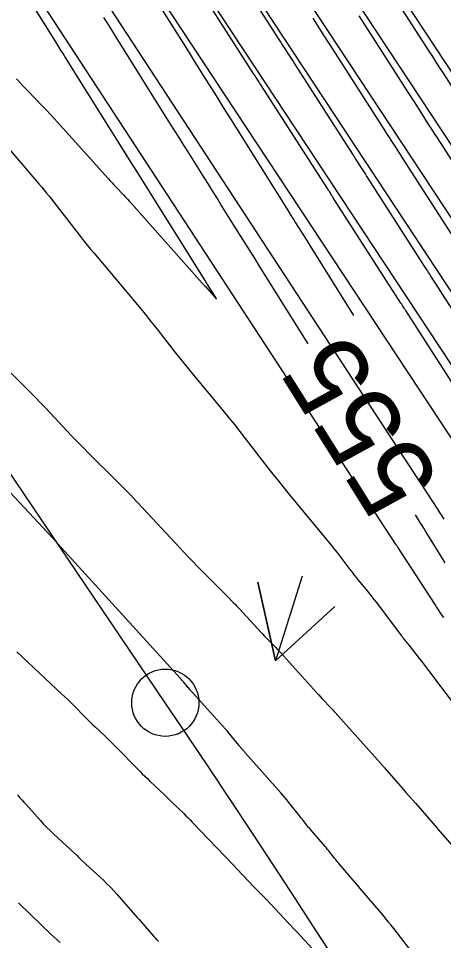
# Model space of a CAD drawing. Extents: x 954385 to 988206, y 1868364 to 1924553.
# Drawn here: x 957686 to 957717.7, y 1920041.8 to 1920110.4 of the extents above; entities that cross this region are included whole.
import ezdxf

# ---------------------------------------------------------------- set-up
doc = ezdxf.new("R2010")
doc.units = 0
for name, color, linetype in [('1', 7, 'Continuous'), ('Default', 7, 'Continuous'), ('Ex_Contour Labels', 7, 'Continuous'), ('Ex_Major Contours', 7, 'Continuous'), ('Ex_Minor Contours', 7, 'Continuous'), ('Prop_Horiz Alignment', 7, 'Continuous'), ('Slopes', 7, 'Continuous')]:
    doc.layers.add(name, color=color, linetype=linetype)

msp = doc.modelspace()

# ---------------------------------------------------------------- linework, layer by layer
at = {"layer": '1'}
for points in [[(957698.283, 1920136.745), (957732.756, 1920084.44)], [(957730.333, 1920082.664), (957695.897, 1920134.914)], [(957693.262, 1920133.461), (957727.911, 1920080.887)], [(957725.489, 1920079.111), (957690.628, 1920132.007)], [(957723.067, 1920077.335), (957687.993, 1920130.554)], [(957720.645, 1920075.559), (957685.358, 1920129.1)], [(957682.718, 1920126.67), (957717.191, 1920073.906), (957717.352, 1920073.659), (957717.513, 1920073.412), (957717.674, 1920073.166)], [(957717.675, 1920065.82), (957717.638, 1920065.877), (957717.411, 1920066.229), (957717.381, 1920066.275), (957717.132, 1920066.659), (957717.022, 1920066.828), (957714.26, 1920071.08), (957714.23, 1920071.126), (957714.2, 1920071.171), (957714.17, 1920071.217), (957714.14, 1920071.263), (957679.353, 1920124.508)], [(957677.043, 1920110.41), (957687.555, 1920098.121), (957687.748, 1920097.893), (957687.939, 1920097.662), (957688.127, 1920097.43), (957688.313, 1920097.195), (957690.738, 1920094.097), (957690.959, 1920093.817), (957691.182, 1920093.539), (957691.408, 1920093.263), (957691.635, 1920092.989), (957695.137, 1920088.81), (957695.465, 1920088.414), (957695.79, 1920088.015), (957696.112, 1920087.614), (957696.429, 1920087.209), (957697.692, 1920085.585), (957698.01, 1920085.18), (957698.33, 1920084.778), (957698.654, 1920084.379), (957698.981, 1920083.981), (957701.267, 1920081.228), (957701.685, 1920080.72), (957702.098, 1920080.209), (957702.507, 1920079.694), (957702.911, 1920079.176), (957704.593, 1920077), (957704.96, 1920076.529), (957705.33, 1920076.062), (957705.704, 1920075.597), (957706.082, 1920075.135), (957709.172, 1920071.381), (957709.308, 1920071.215), (957709.441, 1920071.048), (957709.574, 1920070.88), (957709.705, 1920070.711), (957710.692, 1920069.424), (957710.851, 1920069.219), (957711.011, 1920069.015), (957711.172, 1920068.812), (957711.335, 1920068.61), (957711.99, 1920067.805), (957712.153, 1920067.604), (957712.314, 1920067.4), (957712.474, 1920067.196), (957712.631, 1920066.99), (957714.536, 1920064.478), (957714.567, 1920064.438), (957714.597, 1920064.398), (957714.627, 1920064.358), (957714.657, 1920064.318), (957714.81, 1920064.117), (957714.824, 1920064.097), (957714.839, 1920064.078), (957714.854, 1920064.059), (957714.869, 1920064.04), (957714.93, 1920063.965), (957714.96, 1920063.927), (957714.99, 1920063.889), (957715.869, 1920062.789), (957716.02, 1920062.599), (957716.169, 1920062.408), (957716.317, 1920062.215), (957716.463, 1920062.021), (957718.51, 1920059.276)], [(957715.109, 1920041.194), (957713.947, 1920042.705), (957713.747, 1920042.963), (957713.543, 1920043.218), (957713.337, 1920043.47), (957713.128, 1920043.72), (957711.45, 1920045.696), (957711.277, 1920045.9), (957711.105, 1920046.103), (957710.931, 1920046.305), (957710.758, 1920046.508), (957709.899, 1920047.511), (957709.808, 1920047.618), (957709.719, 1920047.725), (957709.632, 1920047.834), (957709.545, 1920047.943), (957709.201, 1920048.384), (957709.114, 1920048.493), (957709.026, 1920048.602), (957708.937, 1920048.709), (957708.846, 1920048.815), (957707.777, 1920050.051), (957707.698, 1920050.144), (957707.62, 1920050.237), (957707.542, 1920050.332), (957707.466, 1920050.428), (957707.163, 1920050.812), (957707.088, 1920050.908), (957707.012, 1920051.004), (957706.936, 1920051.099), (957706.86, 1920051.195), (957706.143, 1920052.096), (957705.997, 1920052.277), (957705.849, 1920052.456), (957705.698, 1920052.634), (957705.545, 1920052.809), (957702.934, 1920055.769), (957702.897, 1920055.811), (957702.859, 1920055.853), (957702.822, 1920055.896), (957702.784, 1920055.938), (957702.582, 1920056.165), (957702.571, 1920056.178), (957702.56, 1920056.191), (957702.549, 1920056.205), (957702.538, 1920056.218), (957702.484, 1920056.285), (957702.451, 1920056.326), (957701.861, 1920057.054), (957701.758, 1920057.179), (957701.654, 1920057.303), (957701.548, 1920057.425), (957701.44, 1920057.546), (957698.763, 1920060.519), (957698.704, 1920060.585), (957698.647, 1920060.651), (957698.59, 1920060.718), (957698.533, 1920060.786), (957698.31, 1920061.058), (957698.254, 1920061.125), (957698.197, 1920061.192), (957698.139, 1920061.258), (957698.08, 1920061.324), (957688.977, 1920071.325), (957688.97, 1920071.332), (957688.939, 1920071.367), (957688.931, 1920071.375), (957682.191, 1920078.59)], [(957685.956, 1920052.648), (957686.119, 1920052.468), (957686.282, 1920052.287), (957686.445, 1920052.107), (957686.608, 1920051.926), (957687.674, 1920050.742), (957687.909, 1920050.487), (957688.15, 1920050.238), (957688.397, 1920049.995), (957688.649, 1920049.758), (957690.293, 1920048.25), (957690.32, 1920048.224), (957690.347, 1920048.198), (957690.373, 1920048.171), (957690.398, 1920048.143), (957690.5, 1920048.028), (957690.525, 1920048.001), (957690.549, 1920047.976), (957690.575, 1920047.95), (957690.601, 1920047.926), (957690.706, 1920047.828), (957690.732, 1920047.804), (957690.759, 1920047.78), (957690.785, 1920047.755), (957690.811, 1920047.731), (957692.355, 1920046.296), (957692.617, 1920046.045), (957692.873, 1920045.788), (957693.123, 1920045.525), (957693.365, 1920045.255), (957694.867, 1920043.54), (957695.014, 1920043.372), (957695.161, 1920043.204), (957695.307, 1920043.036), (957695.454, 1920042.868), (957696.113, 1920042.109), (957696.223, 1920041.984), (957696.337, 1920041.862), (957696.453, 1920041.743)]]:
    msp.add_lwpolyline(points, dxfattribs=at)
at = {"layer": 'Default'}
msp.add_line((957696.959, 1920059.51), (957504.115, 1920344.606), dxfattribs=at)
msp.add_arc((956871.597, 1919501.221), 996.448, 12.648055, 34.075074, dxfattribs=at)
at = {"layer": 'Ex_Major Contours'}
for points in [[(957707.595, 1920086.214), (957703.976, 1920091.998), (957703.634, 1920092.544), (957703.292, 1920093.091), (957702.949, 1920093.637), (957702.607, 1920094.183), (957701.095, 1920096.598), (957700.784, 1920097.095), (957700.473, 1920097.592), (957700.161, 1920098.09), (957699.85, 1920098.587), (957698.604, 1920100.576), (957698.292, 1920101.074), (957697.981, 1920101.571), (957697.67, 1920102.068), (957697.358, 1920102.566), (957693.234, 1920109.157), (957692.953, 1920109.605), (957692.673, 1920110.053), (957692.392, 1920110.501)], [(957711.355, 1920110.617), (957711.571, 1920110.279), (957711.788, 1920109.941), (957714.673, 1920105.447), (957714.881, 1920105.123), (957715.09, 1920104.798), (957715.298, 1920104.473), (957715.506, 1920104.147), (957716.337, 1920102.847), (957716.545, 1920102.521), (957716.753, 1920102.196), (957716.961, 1920101.871), (957717.17, 1920101.546), (957720.151, 1920096.897)], [(957682.47, 1920086.987), (957686.457, 1920083.067), (957686.866, 1920082.661), (957687.271, 1920082.251), (957687.671, 1920081.837), (957688.068, 1920081.419), (957689.646, 1920079.74), (957690.043, 1920079.322), (957690.443, 1920078.907), (957690.846, 1920078.496), (957691.252, 1920078.087), (957693.386, 1920075.962), (957693.876, 1920075.47), (957694.36, 1920074.973), (957694.839, 1920074.472), (957695.314, 1920073.965), (957698.013, 1920071.056), (957698.34, 1920070.706), (957698.669, 1920070.36), (957699.002, 1920070.016), (957699.338, 1920069.676), (957701.135, 1920067.868), (957701.248, 1920067.754), (957701.362, 1920067.64), (957701.475, 1920067.525), (957701.588, 1920067.411), (957702.042, 1920066.953), (957702.154, 1920066.838), (957702.266, 1920066.722), (957702.377, 1920066.605), (957702.486, 1920066.487), (957704.087, 1920064.745), (957704.205, 1920064.618), (957704.324, 1920064.492), (957704.444, 1920064.367), (957704.565, 1920064.243), (957705.051, 1920063.748), (957705.172, 1920063.623), (957705.291, 1920063.498), (957705.41, 1920063.371), (957705.527, 1920063.243), (957708.206, 1920060.274), (957708.247, 1920060.229), (957708.287, 1920060.183), (957708.328, 1920060.138), (957708.369, 1920060.092), (957708.594, 1920059.838), (957708.603, 1920059.828), (957708.612, 1920059.818), (957708.621, 1920059.808), (957708.63, 1920059.799), (957708.677, 1920059.751), (957708.705, 1920059.722), (957709.228, 1920059.179), (957709.318, 1920059.084), (957709.407, 1920058.989), (957709.495, 1920058.893), (957709.582, 1920058.796), (957712.952, 1920055.002), (957712.977, 1920054.974), (957713.002, 1920054.946), (957713.027, 1920054.919), (957713.053, 1920054.892), (957713.155, 1920054.783), (957713.18, 1920054.756), (957713.205, 1920054.728), (957713.23, 1920054.701), (957713.255, 1920054.673), (957714.623, 1920053.109), (957714.859, 1920052.839), (957715.094, 1920052.569), (957715.33, 1920052.299), (957715.565, 1920052.028), (957717.18, 1920050.167), (957717.193, 1920050.151), (957717.207, 1920050.136), (957717.235, 1920050.106), (957717.242, 1920050.099), (957717.249, 1920050.091), (957717.256, 1920050.083), (957717.263, 1920050.076), (957718.271, 1920048.905)], [(957717.781, 1920069.93), (957716.406, 1920072.138), (957716.291, 1920072.323), (957716.176, 1920072.508), (957716.06, 1920072.692), (957715.945, 1920072.877), (957715.555, 1920073.5)]]:
    msp.add_lwpolyline(points, dxfattribs=at)
at = {"layer": 'Ex_Minor Contours'}
for points in [[(957685.882, 1920105.944), (957686.157, 1920105.648), (957686.435, 1920105.353), (957686.714, 1920105.06), (957687.836, 1920103.894), (957688.115, 1920103.601), (957688.392, 1920103.306), (957688.666, 1920103.009), (957688.938, 1920102.709), (957692.714, 1920098.512), (957692.855, 1920098.356), (957692.998, 1920098.201), (957693.141, 1920098.047), (957693.286, 1920097.894), (957693.866, 1920097.284), (957694.01, 1920097.13), (957694.153, 1920096.976), (957694.295, 1920096.82), (957694.436, 1920096.664), (957699.703, 1920090.734), (957699.722, 1920090.712), (957699.742, 1920090.69), (957699.763, 1920090.668), (957699.783, 1920090.646), (957699.864, 1920090.56), (957699.885, 1920090.538), (957699.905, 1920090.516), (957699.925, 1920090.494), (957699.944, 1920090.472), (957700.631, 1920089.694), (957700.725, 1920089.594), (957700.764, 1920089.566), (957700.749, 1920089.611), (957700.679, 1920089.73), (957699.984, 1920090.841), (957699.927, 1920090.933), (957694.739, 1920099.216), (957694.667, 1920099.33), (957694.596, 1920099.444), (957689.492, 1920107.599), (957689.426, 1920107.706), (957689.359, 1920107.812), (957689.293, 1920107.919), (957689.226, 1920108.025), (957688.892, 1920108.557), (957688.693, 1920108.877), (957684.243, 1920115.982)], [(957721.842, 1920083.274), (957717.409, 1920090.18), (957717.322, 1920090.315), (957717.235, 1920090.45), (957717.149, 1920090.585), (957717.062, 1920090.72), (957716.717, 1920091.26), (957716.63, 1920091.395), (957716.544, 1920091.53), (957716.457, 1920091.665), (957716.371, 1920091.8), (957712.024, 1920098.578), (957711.93, 1920098.724), (957711.837, 1920098.871), (957711.743, 1920099.017), (957711.65, 1920099.163), (957711.276, 1920099.747), (957711.182, 1920099.894), (957711.089, 1920100.04), (957710.995, 1920100.186), (957710.901, 1920100.332), (957706.637, 1920106.975), (957706.536, 1920107.132), (957706.435, 1920107.29), (957706.335, 1920107.447), (957706.234, 1920107.604), (957705.831, 1920108.234), (957705.731, 1920108.391), (957705.63, 1920108.549), (957705.529, 1920108.706), (957705.428, 1920108.863), (957701.251, 1920115.372)], [(957719.947, 1920080.734), (957714.837, 1920088.694), (957714.808, 1920088.741), (957714.778, 1920088.787), (957714.748, 1920088.834), (957714.718, 1920088.88), (957714.599, 1920089.066), (957714.54, 1920089.159), (957714.48, 1920089.251), (957709.451, 1920097.094), (957709.414, 1920097.151), (957709.378, 1920097.208), (957709.342, 1920097.264), (957709.306, 1920097.321), (957709.161, 1920097.548), (957709.125, 1920097.604), (957709.088, 1920097.661), (957709.052, 1920097.717), (957709.016, 1920097.774), (957704.061, 1920105.492), (957704.019, 1920105.559), (957703.976, 1920105.626), (957703.933, 1920105.693), (957703.89, 1920105.76), (957703.719, 1920106.028), (957703.676, 1920106.095), (957703.633, 1920106.162), (957703.59, 1920106.229), (957703.547, 1920106.296), (957698.673, 1920113.89)], [(957714.364, 1920111.425), (957716.559, 1920108.005), (957716.824, 1920107.591), (957717.09, 1920107.176), (957717.355, 1920106.762), (957717.621, 1920106.347), (957718.681, 1920104.688)], [(957710.983, 1920088.335), (957707.723, 1920093.545), (957707.499, 1920093.902), (957707.276, 1920094.259), (957706.677, 1920095.216), (957706.605, 1920095.332), (957706.532, 1920095.448), (957706.278, 1920095.854), (957706.241, 1920095.912), (957701.833, 1920102.952), (957701.294, 1920103.812), (957700.756, 1920104.672), (957699.679, 1920106.391), (957699.41, 1920106.821), (957699.141, 1920107.251), (957698.872, 1920107.681), (957698.603, 1920108.111), (957696.774, 1920111.033)], [(957718.261, 1920094.349), (957714.597, 1920100.062), (957714.446, 1920100.298), (957714.295, 1920100.533), (957714.144, 1920100.769), (957713.993, 1920101.005), (957713.391, 1920101.947), (957713.24, 1920102.183), (957713.089, 1920102.419), (957712.938, 1920102.654), (957712.787, 1920102.89), (957709.213, 1920108.458), (957709.054, 1920108.706), (957708.895, 1920108.953), (957708.736, 1920109.201), (957708.578, 1920109.449), (957707.944, 1920110.44)], [(957685.912, 1920063.298), (957689.27, 1920060.159), (957689.486, 1920059.955), (957689.7, 1920059.749), (957689.912, 1920059.542), (957690.122, 1920059.332), (957691.027, 1920058.418), (957691.202, 1920058.243), (957691.379, 1920058.069), (957691.557, 1920057.897), (957691.736, 1920057.727), (957692.457, 1920057.048), (957692.637, 1920056.877), (957692.814, 1920056.705), (957692.99, 1920056.531), (957693.165, 1920056.355), (957695.067, 1920054.418), (957695.251, 1920054.232), (957695.436, 1920054.048), (957695.623, 1920053.866), (957695.812, 1920053.686), (957696.914, 1920052.641), (957696.931, 1920052.624), (957696.948, 1920052.608), (957696.965, 1920052.592), (957696.982, 1920052.576), (957697.049, 1920052.51), (957697.066, 1920052.494), (957697.082, 1920052.477), (957697.099, 1920052.461), (957697.115, 1920052.444), (957697.295, 1920052.26), (957697.33, 1920052.224), (957697.366, 1920052.189), (957697.402, 1920052.153), (957697.438, 1920052.118), (957698.331, 1920051.258), (957698.491, 1920051.103), (957698.65, 1920050.945), (957698.806, 1920050.786), (957698.962, 1920050.626), (957701.4, 1920048.076), (957701.624, 1920047.841), (957701.848, 1920047.605), (957702.072, 1920047.369), (957702.295, 1920047.133), (957703.539, 1920045.812), (957703.586, 1920045.763), (957703.633, 1920045.714), (957703.681, 1920045.665), (957703.73, 1920045.617), (957703.931, 1920045.419), (957703.976, 1920045.375), (957704.021, 1920045.33), (957704.066, 1920045.286), (957704.111, 1920045.242), (957704.29, 1920045.064), (957704.335, 1920045.02), (957704.379, 1920044.975), (957704.423, 1920044.929), (957704.466, 1920044.883), (957705.791, 1920043.463), (957706.026, 1920043.211), (957706.261, 1920042.959), (957706.495, 1920042.706), (957706.73, 1920042.453), (957710.479, 1920038.405)], [(957689.135, 1920041.66), (957688.916, 1920041.862), (957688.698, 1920042.066), (957688.482, 1920042.272), (957686.083, 1920044.582), (957686.059, 1920044.605), (957686.034, 1920044.628)]]:
    msp.add_lwpolyline(points, dxfattribs=at)
at = {"layer": 'Prop_Horiz Alignment'}
msp.add_circle((957696.959, 1920059.51), 2.5, dxfattribs=at)
at = {"layer": 'Slopes'}
msp.add_lwpolyline([(957707.131, 1920068.928), (957705.147, 1920062.629), (957703.846, 1920068.486), (957705.147, 1920062.629), (957709.569, 1920066.684)], dxfattribs=at)

# ---------------------------------------------------------------- texts
at = {"layer": 'Ex_Contour Labels'}
msp.add_text('555', height=6, rotation=122.05009, dxfattribs=at).set_placement((957717.529, 1920076))

doc.saveas('drawing.dxf')
